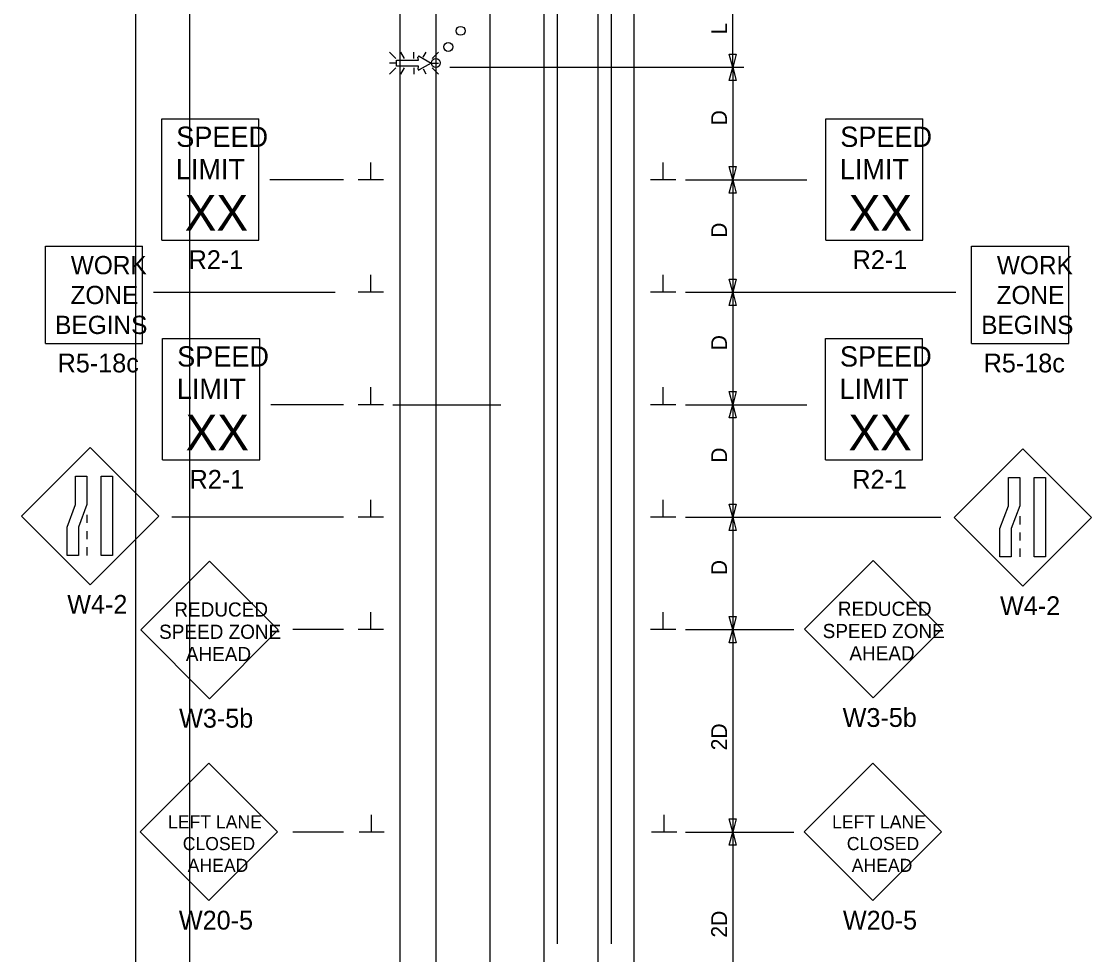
# Model space of a CAD drawing. Extents: x 16576 to 19508, y 5728 to 6974.
# Drawn here: x 16742.5 to 17218.3, y 6151.1 to 6566.1 of the extents above; entities that cross this region are included whole.
import ezdxf

# ---------------------------------------------------------------- set-up
doc = ezdxf.new("R2010")
doc.units = 0
for name, color, linetype in [('ALI_LEGAL_EX', 7, 'Continuous'), ('PAVT_EDGE_EX', 7, 'Continuous'), ('TRAFFIC_SIGNS_PR', 7, 'Continuous'), ('TYPICAL_TEXT_DIMEN_PR', 7, 'Continuous')]:
    doc.layers.add(name, color=color, linetype=linetype)

msp = doc.modelspace()

# ---------------------------------------------------------------- linework, layer by layer
at = {"layer": 'ALI_LEGAL_EX'}
for p, q in [((16980.68, 6974.12), (16980.68, 6155.98)), ((17004.68, 6974.12), (17004.68, 6155.98)), ((16950.77, 6911.88), (16950.77, 6082.69)), ((16974.77, 6911.88), (16974.77, 6082.69)), ((16793.2, 6891.57), (16793.2, 6027.66)), ((16817.2, 6891.57), (16817.2, 6027.66))]:
    msp.add_line(p, q, dxfattribs=at)
for points in [[(16950.77, 6511.88), (16950.77, 6486.88)], [(16974.77, 6511.88), (16974.77, 6486.88)], [(16950.77, 6411.88), (16950.77, 6386.88)], [(16974.77, 6411.88), (16974.77, 6386.88)], [(16950.77, 6311.88), (16950.77, 6286.88)], [(16974.77, 6311.88), (16974.77, 6286.88)], [(16950.77, 6211.88), (16950.77, 6186.88)], [(16974.77, 6211.88), (16974.77, 6186.88)]]:
    msp.add_lwpolyline(points, dxfattribs=at)
at = {"layer": 'PAVT_EDGE_EX'}
for p, q in [((16910.77, 6923.28), (16910.77, 5986.88)), ((16926.77, 6923.28), (16926.77, 5986.88)), ((16998.77, 6923.28), (16998.77, 5986.88)), ((17014.77, 6923.28), (17014.77, 5986.88))]:
    msp.add_line(p, q, dxfattribs=at)
at = {"layer": 'TRAFFIC_SIGNS_PR'}
for p, q in [((16908.93, 6549.55), (16906.11, 6552.38)), ((16912.88, 6549.55), (16911.26, 6552.37)), ((16917.02, 6549.55), (16917.02, 6552.37)), ((16921.2, 6550.19), (16922.46, 6552.37)), ((16927.92, 6552.37), (16925.1, 6549.55)), ((16908.93, 6547.52), (16906.11, 6547.52)), ((16908.93, 6545.49), (16906.11, 6542.67)), ((16911.23, 6542.67), (16912.86, 6545.49)), ((16917.02, 6545.49), (16917.02, 6542.67)), ((16922.49, 6542.67), (16921.28, 6544.76)), ((16925.1, 6547.52), (16927.92, 6547.52)), ((16927.92, 6542.67), (16925.1, 6545.49)), ((16804.87, 6522.81), (16848.07, 6522.81)), ((16804.87, 6468.81), (16804.87, 6522.81)), ((16848.07, 6468.81), (16848.07, 6522.81)), ((17100.11, 6522.81), (17143.31, 6522.81)), ((17100.11, 6468.81), (17100.11, 6522.81)), ((17143.31, 6468.81), (17143.31, 6522.81)), ((16804.87, 6468.81), (16848.07, 6468.81)), ((17100.11, 6468.81), (17143.31, 6468.81)), ((16753.21, 6422.87), (16753.21, 6466.07)), ((16753.21, 6466.07), (16796.41, 6466.07)), ((16796.41, 6422.87), (16796.41, 6466.07)), ((17164.97, 6422.87), (17164.97, 6466.07)), ((17164.97, 6466.07), (17208.17, 6466.07)), ((17208.17, 6422.87), (17208.17, 6466.07)), ((16805.28, 6425.14), (16848.48, 6425.14)), ((16805.28, 6371.14), (16805.28, 6425.14)), ((16848.48, 6371.14), (16848.48, 6425.14)), ((17099.96, 6425.14), (17143.16, 6425.14)), ((17099.96, 6371.14), (17099.96, 6425.14)), ((17143.16, 6371.14), (17143.16, 6425.14)), ((16753.21, 6422.87), (16796.41, 6422.87)), ((17164.97, 6422.87), (17208.17, 6422.87)), ((16773.05, 6376.65), (16742.5, 6346.1)), ((16803.59, 6346.1), (16773.05, 6376.65)), ((17187.8, 6376.04), (17157.25, 6345.5)), ((17218.35, 6345.5), (17187.8, 6376.04)), ((16805.28, 6371.14), (16848.48, 6371.14)), ((17099.96, 6371.14), (17143.16, 6371.14)), ((16742.5, 6346.1), (16773.05, 6315.56)), ((16771.64, 6346.66), (16771.64, 6343.06)), ((16773.05, 6315.56), (16803.59, 6346.1)), ((17157.25, 6345.5), (17187.8, 6314.95)), ((17186.4, 6346.05), (17186.4, 6342.45)), ((17187.8, 6314.95), (17218.35, 6345.5)), ((16771.64, 6339.46), (16771.64, 6335.86)), ((17186.4, 6338.85), (17186.4, 6335.25)), ((16771.64, 6332.26), (16771.64, 6328.66)), ((17186.4, 6331.65), (17186.4, 6328.05)), ((16826.17, 6326.02), (16795.63, 6295.47)), ((16856.72, 6295.47), (16826.17, 6326.02)), ((17121.22, 6326.35), (17090.67, 6295.8)), ((17151.76, 6295.8), (17121.22, 6326.35)), ((16795.63, 6295.47), (16826.17, 6264.92)), ((16826.17, 6264.92), (16856.72, 6295.47)), ((17090.67, 6295.8), (17121.22, 6265.25)), ((17121.22, 6265.25), (17151.76, 6295.8)), ((16825.82, 6236.24), (16795.27, 6205.69)), ((16856.37, 6205.69), (16825.82, 6236.24)), ((17121.09, 6236.24), (17090.54, 6205.69)), ((17151.63, 6205.69), (17121.09, 6236.24)), ((16795.27, 6205.69), (16825.82, 6175.14)), ((16825.82, 6175.14), (16856.37, 6205.69)), ((17090.54, 6205.69), (17121.09, 6175.14)), ((17121.09, 6175.14), (17151.63, 6205.69))]:
    msp.add_line(p, q, dxfattribs=at)
for points in [[(16918.85, 6544.84), (16919.07, 6546.14), (16909.35, 6546.14), (16909.35, 6548.88), (16919.07, 6548.88), (16918.84, 6550.18)], [(16919.35, 6550.54), (16924.65, 6547.52), (16919.34, 6544.48)]]:
    msp.add_lwpolyline(points, dxfattribs=at)
for points in [[(16771.64, 6363.81), (16771.64, 6351.23), (16767.88, 6341.24), (16767.88, 6328.66), (16762.83, 6328.66), (16762.83, 6341.24), (16766.59, 6351.23), (16766.59, 6363.81)], [(16783.05, 6363.81), (16783.05, 6328.66), (16777.99, 6328.66), (16777.99, 6363.81)], [(17186.4, 6363.2), (17186.4, 6350.62), (17182.63, 6340.63), (17182.63, 6328.05), (17177.58, 6328.05), (17177.58, 6340.63), (17181.34, 6350.62), (17181.34, 6363.2)], [(17197.8, 6363.2), (17197.8, 6328.05), (17192.74, 6328.05), (17192.74, 6363.2)]]:
    msp.add_lwpolyline(points, close=True, dxfattribs=at)
for centre in [(16937.77, 6561.87), (16932.27, 6554.74), (16926.77, 6547.62)]:
    msp.add_circle(centre, 2, dxfattribs=at)
for centre, start, end in [((16919.18, 6550.24), 61.1084, 189.2692), ((16919.18, 6544.78), 170.0407, 298.5167)]:
    msp.add_arc(centre, 0.341, start, end, dxfattribs=at)
at = {"layer": 'TYPICAL_TEXT_DIMEN_PR'}
for p, q in [((17058.77, 6545.62), (17058.77, 6576.13)), ((17058.77, 6545.62), (17057.2, 6551.48)), ((17057.2, 6551.48), (17058.77, 6551.48)), ((17058.77, 6551.48), (17060.34, 6551.48)), ((17060.34, 6551.48), (17058.77, 6545.62)), ((17063.77, 6545.62), (16933.03, 6545.62)), ((17057.2, 6539.76), (17058.77, 6545.62)), ((17058.77, 6545.62), (17058.77, 6495.62)), ((17058.77, 6545.62), (17060.34, 6539.76)), ((17058.77, 6539.76), (17057.2, 6539.76)), ((17060.34, 6539.76), (17058.77, 6539.76)), ((16897.85, 6495.62), (16897.85, 6503.4)), ((17027.9, 6495.62), (17027.9, 6503.4)), ((17058.77, 6495.62), (17057.2, 6501.48)), ((17057.2, 6501.48), (17058.77, 6501.48)), ((17058.77, 6501.48), (17060.34, 6501.48)), ((17060.34, 6501.48), (17058.77, 6495.62)), ((16885.71, 6495.62), (16852.97, 6495.62)), ((16903.47, 6495.62), (16892.22, 6495.62)), ((17033.52, 6495.62), (17022.27, 6495.62)), ((17037.77, 6495.62), (17091.71, 6495.62)), ((17057.2, 6489.76), (17058.77, 6495.62)), ((17058.77, 6495.62), (17058.77, 6445.62)), ((17058.77, 6495.62), (17060.34, 6489.76)), ((17058.77, 6489.76), (17057.2, 6489.76)), ((17060.34, 6489.76), (17058.77, 6489.76)), ((16897.85, 6445.62), (16897.85, 6453.4)), ((17027.9, 6445.62), (17027.9, 6453.4)), ((17058.77, 6445.62), (17057.2, 6451.48)), ((17057.2, 6451.48), (17058.77, 6451.48)), ((17058.77, 6451.48), (17060.34, 6451.48)), ((17060.34, 6451.48), (17058.77, 6445.62)), ((16801.22, 6445.62), (16882.03, 6445.62)), ((16903.47, 6445.62), (16892.22, 6445.62)), ((17033.52, 6445.62), (17022.27, 6445.62)), ((17037.77, 6445.62), (17157.94, 6445.62)), ((17037.77, 6445.62), (17047.02, 6445.62)), ((17057.2, 6439.76), (17058.77, 6445.62)), ((17058.77, 6445.62), (17060.34, 6439.76)), ((17058.77, 6445.62), (17058.77, 6395.62)), ((17058.77, 6439.76), (17057.2, 6439.76)), ((17060.34, 6439.76), (17058.77, 6439.76)), ((16897.85, 6395.62), (16897.85, 6403.4)), ((17027.9, 6395.62), (17027.9, 6403.4)), ((17058.77, 6395.62), (17057.2, 6401.48)), ((17057.2, 6401.48), (17058.77, 6401.48)), ((17058.77, 6401.48), (17060.34, 6401.48)), ((17060.34, 6401.48), (17058.77, 6395.62)), ((16885.71, 6395.62), (16853.48, 6395.62)), ((16903.47, 6395.62), (16892.22, 6395.62)), ((16907.72, 6395.62), (16955.67, 6395.62)), ((17033.52, 6395.62), (17022.27, 6395.62)), ((17037.77, 6395.62), (17091.71, 6395.62)), ((17057.2, 6389.76), (17058.77, 6395.62)), ((17058.77, 6395.62), (17058.77, 6345.62)), ((17058.77, 6395.62), (17060.34, 6389.76)), ((17058.77, 6389.76), (17057.2, 6389.76)), ((17060.34, 6389.76), (17058.77, 6389.76)), ((16897.85, 6345.62), (16897.85, 6353.4)), ((17027.9, 6345.62), (17027.9, 6353.4)), ((17058.77, 6345.62), (17057.2, 6351.48)), ((17057.2, 6351.48), (17058.77, 6351.48)), ((17058.77, 6351.48), (17060.34, 6351.48)), ((17060.34, 6351.48), (17058.77, 6345.62)), ((16885.71, 6345.62), (16809.44, 6345.62)), ((16903.47, 6345.62), (16892.22, 6345.62)), ((17033.52, 6345.62), (17022.27, 6345.62)), ((17037.77, 6345.62), (17151.35, 6345.62)), ((17037.77, 6345.62), (17047.02, 6345.62)), ((17057.2, 6339.76), (17058.77, 6345.62)), ((17058.77, 6345.62), (17060.34, 6339.76)), ((17058.77, 6345.62), (17058.77, 6295.62)), ((17058.77, 6339.76), (17057.2, 6339.76)), ((17060.34, 6339.76), (17058.77, 6339.76)), ((16897.85, 6295.62), (16897.85, 6303.4)), ((17027.9, 6295.62), (17027.9, 6303.4)), ((17058.77, 6295.62), (17057.2, 6301.48)), ((17057.2, 6301.48), (17058.77, 6301.48)), ((17058.77, 6301.48), (17060.34, 6301.48)), ((17060.34, 6301.48), (17058.77, 6295.62)), ((16885.71, 6295.62), (16863.25, 6295.62)), ((16903.47, 6295.62), (16892.22, 6295.62)), ((17033.52, 6295.62), (17022.27, 6295.62)), ((17037.77, 6295.62), (17085.95, 6295.62)), ((17037.77, 6295.62), (17047.02, 6295.62)), ((17057.2, 6289.76), (17058.77, 6295.62)), ((17058.77, 6295.62), (17058.77, 6205.62)), ((17058.77, 6295.62), (17060.34, 6289.76)), ((17058.77, 6289.76), (17057.2, 6289.76)), ((17060.34, 6289.76), (17058.77, 6289.76)), ((16898.24, 6205.57), (16898.24, 6213.35)), ((17028.29, 6205.57), (17028.29, 6213.35)), ((17058.77, 6205.62), (17057.2, 6211.48)), ((17057.2, 6211.48), (17058.77, 6211.48)), ((17058.77, 6211.48), (17060.34, 6211.48)), ((17060.34, 6211.48), (17058.77, 6205.62)), ((16885.71, 6205.62), (16863.25, 6205.62)), ((16903.87, 6205.57), (16892.62, 6205.57)), ((17033.92, 6205.57), (17022.67, 6205.57)), ((17037.77, 6205.62), (17085.95, 6205.62)), ((17057.2, 6199.76), (17058.77, 6205.62)), ((17058.77, 6205.62), (17058.77, 6115.62)), ((17058.77, 6205.62), (17060.34, 6199.76)), ((17058.77, 6199.76), (17057.2, 6199.76)), ((17060.34, 6199.76), (17058.77, 6199.76))]:
    msp.add_line(p, q, dxfattribs=at)

# ---------------------------------------------------------------- texts
at = {"layer": 'TRAFFIC_SIGNS_PR'}
for s, height, p in [('SPEED', 9, (16811.36, 6510.28)), ('SPEED', 9, (17106.6, 6510.28)), ('LIMIT', 9, (16811.18, 6495.88)), ('LIMIT', 9, (17106.41, 6495.88)), ('XX', 15.785, (16815.13, 6473.03)), ('XX', 15.785, (17110.36, 6473.03)), ('R2-1', 8.37, (16816.88, 6455.94)), ('R2-1', 8.37, (17112.12, 6455.94)), ('WORK', 8.119, (16764.46, 6453.65)), ('WORK', 8.119, (17176.22, 6453.65)), ('ZONE', 8.119, (16764.33, 6440.37)), ('ZONE', 8.119, (17176.09, 6440.37)), ('BEGINS', 8.119, (16757.5, 6427.08)), ('BEGINS', 8.119, (17169.26, 6427.08)), ('SPEED', 9, (16811.77, 6412.61)), ('SPEED', 9, (17106.45, 6412.61)), ('R5-18c', 8.37, (16758.63, 6410)), ('R5-18c', 8.37, (17170.38, 6410)), ('LIMIT', 9, (16811.59, 6398.21)), ('LIMIT', 9, (17106.27, 6398.21)), ('XX', 15.785, (16815.53, 6375.37)), ('XX', 15.785, (17110.22, 6375.37)), ('R2-1', 8.37, (16817.29, 6358.27)), ('R2-1', 8.37, (17111.98, 6358.27)), ('W4-2', 8.37, (16762.88, 6302.69)), ('W4-2', 8.37, (17177.63, 6302.08)), ('REDUCED', 6.3, (16810.49, 6301.44)), ('REDUCED', 6.3, (17105.53, 6301.77)), ('SPEED ZONE', 6.3, (16803.73, 6291.54)), ('SPEED ZONE', 6.3, (17098.77, 6291.87)), ('AHEAD', 6.3, (16815.61, 6281.64)), ('AHEAD', 6.3, (17110.65, 6281.97)), ('W3-5b', 8.37, (16812.62, 6252.05)), ('W3-5b', 8.37, (17107.66, 6252.38)), ('LEFT LANE', 5.85, (16807.69, 6207.26)), ('LEFT LANE', 5.85, (17102.95, 6207.26)), ('CLOSED', 5.85, (16814.25, 6197.58)), ('CLOSED', 5.85, (17109.51, 6197.58)), ('AHEAD', 5.85, (16816.44, 6187.91)), ('AHEAD', 5.85, (17111.7, 6187.91)), ('W20-5', 8.37, (16812.52, 6162.27)), ('W20-5', 8.37, (17107.78, 6162.27))]:
    msp.add_text(s, height=height, dxfattribs=at).set_placement(p)
at = {"layer": 'TYPICAL_TEXT_DIMEN_PR'}
for s, p in [('L', (17056.21, 6560.23)), ('D', (17056.21, 6519.84)), ('D', (17056.21, 6469.84)), ('D', (17056.21, 6419.84)), ('D', (17056.21, 6369.84)), ('D', (17056.21, 6319.84)), ('2D', (17056.21, 6241.98)), ('2D', (17056.21, 6158.7))]:
    msp.add_text(s, height=7, rotation=90, dxfattribs=at).set_placement(p)

doc.saveas('drawing.dxf')
